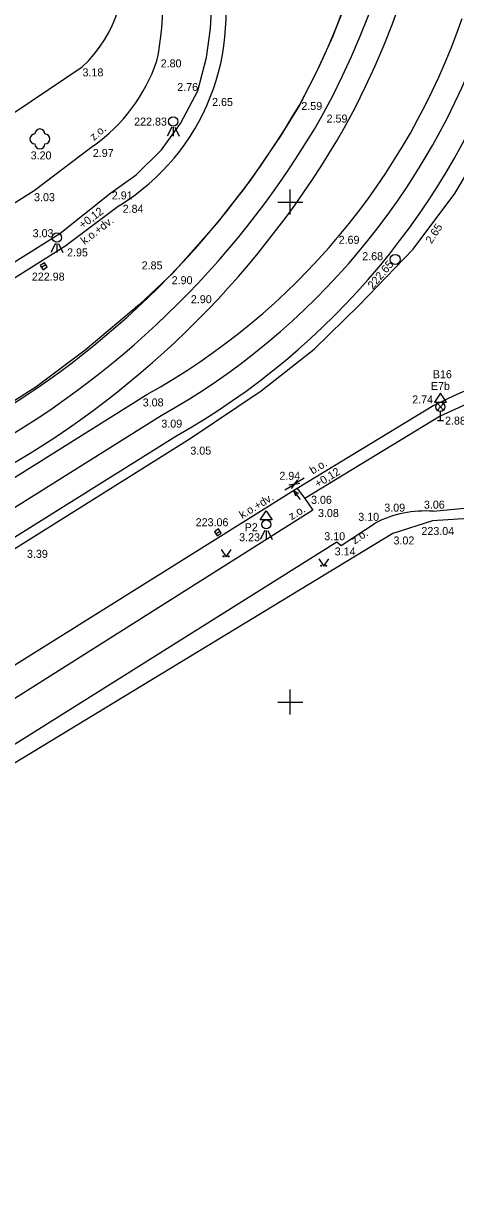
# Model space of a CAD drawing. Extents: x -598741 to -598592, y -1156973 to -1156763.
# Drawn here: x -598663.3 to -598641.7, y -1156924.3 to -1156866.1 of the extents above; entities that cross this region are included whole.
import ezdxf

# ---------------------------------------------------------------- set-up
doc = ezdxf.new("R2010")
doc.units = 0
for name, color, linetype in [('Vrstva 10', 7, 'Continuous'), ('Vrstva 13', 7, 'Continuous'), ('Vrstva 14', 7, 'Continuous'), ('Vrstva 19', 7, 'Continuous'), ('Vrstva 25', 7, 'Continuous'), ('Vrstva 44', 7, 'Continuous'), ('Vrstva 49', 7, 'Continuous'), ('Vrstva 50', 7, 'Continuous'), ('Vrstva 58', 7, 'Continuous'), ('Vrstva 62', 7, 'Continuous'), ('Vrstva 63', 7, 'Continuous'), ('Vrstva 7', 7, 'Continuous')]:
    doc.layers.add(name, color=color, linetype=linetype)

msp = doc.modelspace()

# ---------------------------------------------------------------- linework, layer by layer
at = {"layer": 'Vrstva 10'}
msp.add_line((-598693.59, -1156890.53), (-598660.4, -1156868.25), dxfattribs=at)
msp.add_lwpolyline([(-598621.74, -1156889.58), (-598642.9, -1156890.94), (-598644.87, -1156891.57), (-598666.18, -1156904.5), (-598682.28, -1156914.49), (-598689.54, -1156918.79), (-598690.41, -1156923.11), (-598688.22, -1156929.02)], dxfattribs=at)
msp.add_arc((-598664.846, -1156863.438), 6.551, 312.7345, 13.66876, dxfattribs=at)
at = {"layer": 'Vrstva 13'}
for p, q in [((-598716.756, -1156921.986), (-598657.165, -1156884.63)), ((-598715.375, -1156924.074), (-598655.724, -1156886.71))]:
    msp.add_line(p, q, dxfattribs=at)
for centre, radius, start, end in [((-598684.3, -1156851.077), 42.168, 331.38228, 20.65336), ((-598684.475, -1156851.099), 39.789, 331.38593, 20.59112), ((-598673.908, -1156854.609), 34.374, 299.14988, 340.96763), ((-598673.875, -1156854.607), 36.879, 299.48472, 340.80396), ((-598687.552, -1156848.072), 43.956, 299.6767, 329.84191), ((-598687.332, -1156848.349), 46.146, 299.91163, 330.21126)]:
    msp.add_arc(centre, radius, start, end, dxfattribs=at)
at = {"layer": 'Vrstva 14'}
for points in [[(-598653.46, -1156892.365), (-598653.21, -1156892.74), (-598652.96, -1156892.365)], [(-598648.58, -1156892.835), (-598648.33, -1156893.21), (-598648.08, -1156892.835)]]:
    msp.add_lwpolyline(points, dxfattribs=at)
for centre, radius in [((-598662.51, -1156871.85), 0.00025), ((-598653.335, -1156892.715), 0.025), ((-598653.085, -1156892.715), 0.025), ((-598648.455, -1156893.185), 0.025), ((-598648.205, -1156893.185), 0.025)]:
    msp.add_circle(centre, radius, dxfattribs=at)
for centre, start, end in [((-598662.76, -1156871.85), 89.99999, 269.99999), ((-598662.51, -1156871.6), 0, 179.99999), ((-598662.26, -1156871.85), 270, 89.99999), ((-598662.51, -1156872.1), 179.99999, 359.99999)]:
    msp.add_arc(centre, 0.25, start, end, dxfattribs=at)
at = {"layer": 'Vrstva 19'}
msp.add_line((-598716.065, -1156923.03), (-598656.445, -1156885.67), dxfattribs=at)
for centre, radius, start, end in [((-598684.388, -1156851.088), 40.979, 331.38299, 20.62273), ((-598673.891, -1156854.609), 35.626, 299.3215, 340.88454), ((-598687.439, -1156848.213), 45.047, 299.79577, 330.03181)]:
    msp.add_arc(centre, radius, start, end, dxfattribs=at)
at = {"layer": 'Vrstva 25'}
for p, q in [((-598662.216, -1156878.141), (-598662.424, -1156878.279)), ((-598653.725, -1156891.588), (-598653.515, -1156891.452))]:
    msp.add_line(p, q, dxfattribs=at)
for points in [[(-598662.286, -1156878.036), (-598662.494, -1156878.174), (-598662.355, -1156878.383), (-598662.147, -1156878.245)], [(-598653.657, -1156891.694), (-598653.447, -1156891.558), (-598653.583, -1156891.347), (-598653.793, -1156891.483)]]:
    msp.add_lwpolyline(points, close=True, dxfattribs=at)
msp.add_circle((-598644.76, -1156877.87), 0.25, dxfattribs=at)
at = {"layer": 'Vrstva 44'}
for p, q in [((-598655.924, -1156871.263), (-598656.15, -1156871.715)), ((-598655.85, -1156871.265), (-598655.85, -1156871.715)), ((-598655.775, -1156871.263), (-598655.55, -1156871.715)), ((-598661.734, -1156877.073), (-598661.96, -1156877.525)), ((-598661.66, -1156877.075), (-598661.66, -1156877.525)), ((-598661.585, -1156877.073), (-598661.36, -1156877.525)), ((-598642.35, -1156885.07), (-598642.65, -1156885.414)), ((-598642.65, -1156885.07), (-598642.35, -1156885.414)), ((-598642.5, -1156885.92), (-598642.5, -1156885.47)), ((-598642.65, -1156885.92), (-598642.35, -1156885.92)), ((-598651.275, -1156891.42), (-598651.5, -1156891.87)), ((-598651.2, -1156891.42), (-598651.2, -1156891.87)), ((-598651.125, -1156891.42), (-598650.9, -1156891.87))]:
    msp.add_line(p, q, dxfattribs=at)
msp.add_lwpolyline([(-598642.8, -1156885.014), (-598642.2, -1156885.014), (-598642.5, -1156884.564), (-598642.8, -1156885.014)], dxfattribs=at)
msp.add_lwpolyline([(-598650.897, -1156890.896), (-598651.499, -1156890.896), (-598651.2, -1156890.439)], close=True, dxfattribs=at)
for centre, radius in [((-598655.85, -1156870.97), 0.234), ((-598661.66, -1156876.78), 0.234), ((-598642.5, -1156885.242), 0.228), ((-598651.2, -1156891.12), 0.224)]:
    msp.add_circle(centre, radius, dxfattribs=at)
at = {"layer": 'Vrstva 49'}
for p, q in [((-598649.311, -1156888.815), (-598649.791, -1156889.11)), ((-598649.791, -1156889.11), (-598649.617, -1156888.888)), ((-598649.791, -1156889.11), (-598649.515, -1156889.051)), ((-598650.268, -1156889.398), (-598649.788, -1156889.102)), ((-598649.788, -1156889.102), (-598650.064, -1156889.162)), ((-598649.788, -1156889.102), (-598649.962, -1156889.324)), ((-598649.49, -1156889.876), (-598649.834, -1156889.429)), ((-598649.834, -1156889.429), (-598649.746, -1156889.697)), ((-598649.834, -1156889.429), (-598649.595, -1156889.578))]:
    msp.add_line(p, q, dxfattribs=at)
at = {"layer": 'Vrstva 62'}
for p, q in [((-598650, -1156875.625), (-598650, -1156874.375)), ((-598650.625, -1156875), (-598649.375, -1156875)), ((-598650, -1156900.625), (-598650, -1156899.375)), ((-598650.625, -1156900), (-598649.375, -1156900))]:
    msp.add_line(p, q, dxfattribs=at)
at = {"layer": 'Vrstva 63'}
for points in [[(-598655, -1156886.83), (-598651.46, -1156884.44), (-598648.81, -1156882.36), (-598646.56, -1156880.16), (-598643.86, -1156877.35), (-598641.77, -1156874.58), (-598639.72, -1156871.14), (-598637.35, -1156866.63), (-598636.83, -1156866.43), (-598636.58, -1156865.46), (-598636.34, -1156864.632), (-598636.05, -1156863.52), (-598635.84, -1156862.6), (-598635.59, -1156861.24), (-598632.28, -1156858.94), (-598632.14, -1156858.84), (-598631.83, -1156857.64), (-598631.65, -1156855.47), (-598631.65, -1156853.18), (-598631.79, -1156849.94), (-598632.27, -1156845.78), (-598632.86, -1156842.42), (-598633.67, -1156838.94), (-598634.64, -1156835.55)], [(-598646.62, -1156863.4), (-598647.88, -1156866.71), (-598648.6, -1156868.32), (-598649.546, -1156870.155), (-598650.51, -1156871.73), (-598652, -1156873.923), (-598653.7, -1156876.114), (-598655.85, -1156878.54), (-598657.53, -1156880.12), (-598660.25, -1156882.4), (-598662.72, -1156884.25), (-598666.45, -1156886.63), (-598682.74, -1156896.56), (-598702.24, -1156908.79), (-598715.55, -1156917.14)], [(-598708.08, -1156905.8), (-598661.52, -1156876.57), (-598658.97, -1156874.55), (-598657.7, -1156873.64), (-598656.44, -1156872.39), (-598655.48, -1156871.07), (-598654.62, -1156869.45), (-598654.19, -1156867.78), (-598653.98, -1156866.32), (-598653.91, -1156864.76)], [(-598639.97, -1156884.56), (-598642.51, -1156885.7), (-598649.28, -1156889.83), (-598648.88, -1156890.41), (-598665.92, -1156901.18), (-598683.74, -1156912.35), (-598699.88, -1156922.5), (-598701.13, -1156922.47), (-598704.74, -1156924.93), (-598706.51, -1156926.67), (-598708.08, -1156929.03), (-598708.58, -1156930.282), (-598709.09, -1156932.3), (-598709.75, -1156932.17), (-598711.17, -1156931.77), (-598715.18, -1156924.43), (-598699.21, -1156914.53), (-598663.81, -1156892.35), (-598655, -1156886.83)]]:
    msp.add_lwpolyline(points, dxfattribs=at)
at = {"layer": 'Vrstva 7'}
msp.add_line((-598642.86, -1156890.46), (-598627.05, -1156888.92), dxfattribs=at)
for points in [[(-598659.83, -1156872.2), (-598662.79, -1156874.45), (-598677.32, -1156883.6), (-598696.01, -1156895.4)], [(-598658.54, -1156875.17), (-598661.27, -1156877.23), (-598674.96, -1156885.84), (-598707.02, -1156905.99)], [(-598642.82, -1156885.18), (-598649.66, -1156889.32), (-598666.68, -1156899.98), (-598684.52, -1156911.16), (-598704.18, -1156923.54)], [(-598649.66, -1156889.32), (-598649.28, -1156889.83), (-598648.88, -1156890.41), (-598665.92, -1156901.18), (-598683.74, -1156912.35), (-598699.88, -1156922.5), (-598701.13, -1156922.47), (-598701.82, -1156922.37), (-598701.963, -1156922.144)], [(-598694.25, -1156926.42), (-598690.23, -1156918.73), (-598682.6, -1156913.92), (-598664.75, -1156902.71), (-598647.68, -1156891.99), (-598647.45, -1156892.18), (-598645.76, -1156891.05)]]:
    msp.add_lwpolyline(points, dxfattribs=at)
for centre, radius, start, end in [((-598670.914, -1156865.033), 14.547, 348.47374, 11.91405), ((-598664.394, -1156865.64), 11.185, 301.56073, 15.18571), ((-598665.04, -1156865.013), 8.877, 305.94245, 340.74936), ((-598633.185, -1156903.631), 20.815, 86.26727, 117.57309), ((-598643.256, -1156895.934), 5.488, 85.85774, 117.14181)]:
    msp.add_arc(centre, radius, start, end, dxfattribs=at)

# ---------------------------------------------------------------- texts
at = {"layer": 'Vrstva 49'}
for s, rotation, p in [('z.o.', 40.63194, (-598659.813, -1156871.956)), ('k.o.+dv.', 37.69148, (-598660.279, -1156877.153)), ('b.o.', 31.22491, (-598648.88, -1156888.63)), ('k.o.+dv.', 31.22491, (-598652.4, -1156890.85)), ('z.o.', 31.51407, (-598649.936, -1156890.914)), ('z.o.', 34.58056, (-598646.781, -1156892.132))]:
    msp.add_text(s, height=0.4, rotation=rotation, dxfattribs=at).set_placement(p)
for s, p in [('B16', (-598642.877, -1156883.81)), ('E7b', (-598642.974, -1156884.4)), ('P2', (-598652.28, -1156891.46))]:
    msp.add_text(s, height=0.4, dxfattribs=at).set_placement(p)
at = {"layer": 'Vrstva 50'}
for rotation, p in [(36.78806, (-598660.378, -1156876.358)), (31.56756, (-598648.622, -1156889.297))]:
    msp.add_text('+0,12', height=0.4, rotation=rotation, dxfattribs=at).set_placement(p)
at = {"layer": 'Vrstva 58'}
for s, p in [('2.80', (-598656.476, -1156868.27)), ('3.18', (-598660.38, -1156868.72)), ('2.76', (-598655.646, -1156869.45)), ('2.65', (-598653.906, -1156870.2)), ('2.59', (-598649.446, -1156870.4)), ('222.83', (-598657.802, -1156871.18)), ('2.59', (-598648.186, -1156871.03)), ('3.20', (-598662.972, -1156872.87)), ('2.97', (-598659.866, -1156872.75)), ('2.91', (-598658.916, -1156874.87)), ('3.03', (-598662.802, -1156874.96)), ('2.84', (-598658.376, -1156875.54)), ('3.03', (-598662.872, -1156876.76)), ('2.69', (-598647.583, -1156877.09)), ('2.95', (-598661.153, -1156877.72)), ('2.85', (-598657.426, -1156878.37)), ('2.68', (-598646.403, -1156877.91)), ('222.98', (-598662.912, -1156878.93)), ('2.90', (-598655.926, -1156879.11)), ('2.90', (-598654.966, -1156880.06)), ('3.08', (-598657.372, -1156885.22)), ('2.74', (-598643.906, -1156885.07)), ('3.09', (-598656.442, -1156886.28)), ('2.88', (-598642.266, -1156886.13)), ('3.05', (-598654.992, -1156887.63)), ('2.94', (-598650.546, -1156888.89)), ('3.06', (-598648.962, -1156890.09)), ('3.09', (-598645.302, -1156890.48)), ('3.06', (-598643.322, -1156890.33)), ('223.06', (-598654.727, -1156891.21)), ('3.08', (-598648.614, -1156890.75)), ('3.10', (-598646.601, -1156890.94)), ('223.04', (-598643.447, -1156891.65)), ('3.23', (-598652.554, -1156891.96)), ('3.10', (-598648.301, -1156891.91)), ('3.02', (-598644.842, -1156892.12)), ('3.39', (-598663.157, -1156892.79)), ('3.14', (-598647.781, -1156892.67))]:
    msp.add_text(s, height=0.4, dxfattribs=at).set_placement(p)
for s, rotation, p in [('2.65', 56.59833, (-598642.943, -1156877.117)), ('222.65', 49.75591, (-598645.869, -1156879.382))]:
    msp.add_text(s, height=0.4, rotation=rotation, dxfattribs=at).set_placement(p)

doc.saveas('drawing.dxf')
